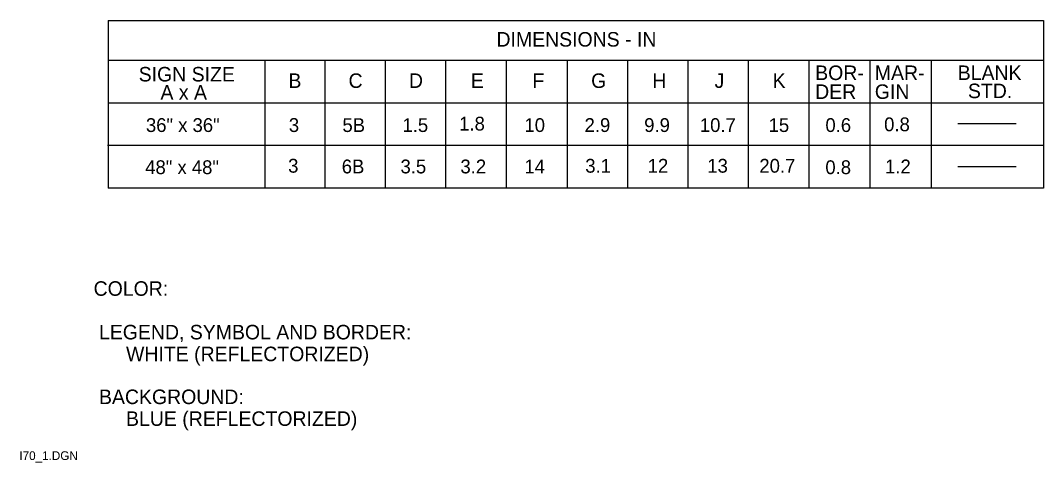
# Model space of a CAD drawing. Extents: x 0.013 to 0.194, y 0.004 to 0.259.
# Drawn here: x 0.0126 to 0.1884, y 0.0039 to 0.08 of the extents above; entities that cross this region are included whole.
import ezdxf

# ---------------------------------------------------------------- set-up
doc = ezdxf.new("R2010")
doc.units = 0
doc.layers.add('1', color=7, linetype='Continuous')
doc.layers.add('3', color=7, linetype='Continuous')

msp = doc.modelspace()

# ---------------------------------------------------------------- linework, layer by layer
at = {"layer": '3'}
for p, q in [((0.02763, 0.08), (0.18838, 0.08)), ((0.02763, 0.08), (0.02763, 0.05113)), ((0.18838, 0.08), (0.18838, 0.05113)), ((0.18838, 0.07312), (0.02763, 0.07312)), ((0.05454, 0.07306), (0.05454, 0.05106)), ((0.06488, 0.07312), (0.06488, 0.05113)), ((0.07525, 0.07312), (0.07525, 0.05113)), ((0.08563, 0.07312), (0.08563, 0.05113)), ((0.096, 0.07312), (0.096, 0.05113)), ((0.1065, 0.07312), (0.1065, 0.05113)), ((0.11688, 0.07312), (0.11688, 0.05113)), ((0.12725, 0.07312), (0.12725, 0.05113)), ((0.13762, 0.07312), (0.13762, 0.05113)), ((0.14804, 0.07306), (0.14804, 0.05106)), ((0.15854, 0.07306), (0.15854, 0.05106)), ((0.16904, 0.07306), (0.16904, 0.05106)), ((0.18838, 0.06575), (0.02763, 0.06575)), ((0.17367, 0.06225), (0.18367, 0.06225)), ((0.18838, 0.0585), (0.0275, 0.0585)), ((0.17367, 0.05488), (0.18367, 0.05488)), ((0.18838, 0.05113), (0.02763, 0.05113))]:
    msp.add_line(p, q, dxfattribs=at)

# ---------------------------------------------------------------- texts
at = {"layer": '1'}
for s, height, p in [('COLOR:', 0.0025, (0.02513, 0.03263)), (' LEGEND, SYMBOL AND BORDER:', 0.0024998, (0.02513, 0.02513)), ('      WHITE (REFLECTORIZED)', 0.0024998, (0.02513, 0.02138)), (' BACKGROUND:', 0.0024998, (0.02513, 0.014)), ('      BLUE (REFLECTORIZED)', 0.0024998, (0.02513, 0.01025))]:
    msp.add_text(s, height=height, dxfattribs=at).set_placement(p)
at = {"layer": '3'}
for s, height, p in [('DIMENSIONS - IN', 0.0024998, (0.09436, 0.0755)), ('BOR-', 0.0025, (0.14913, 0.06975)), ('MAR-', 0.0025, (0.15938, 0.06975)), ('BLANK', 0.0025, (0.17363, 0.06975)), ('SIGN SIZE', 0.0025, (0.03288, 0.0695)), ('B', 0.0025, (0.05861, 0.06839)), ('C', 0.0025, (0.06894, 0.06839)), ('D', 0.0025, (0.07932, 0.06839)), ('E', 0.0025, (0.08996, 0.06839)), ('F', 0.0025, (0.10054, 0.06839)), ('G', 0.0025, (0.11063, 0.06839)), ('H', 0.0025, (0.12114, 0.06839)), ('J', 0.0025, (0.13184, 0.06839)), ('K', 0.0025, (0.14181, 0.06839)), ('A x A', 0.0025, (0.03662, 0.06638)), ('DER', 0.0025, (0.14913, 0.0665)), ('GIN', 0.0025, (0.15938, 0.0665)), ('STD.', 0.0025, (0.17538, 0.06663)), ('1.8', 0.002375, (0.08795, 0.06106)), ('0.8', 0.002375, (0.16098, 0.06094)), ('36" x 36"', 0.002375, (0.03412, 0.06081)), ('3', 0.00238, (0.05868, 0.06081)), ('5B', 0.002375, (0.06789, 0.06081)), ('1.5', 0.002375, (0.07821, 0.06081)), ('10', 0.002375, (0.09917, 0.06081)), ('2.9', 0.002375, (0.1095, 0.06081)), ('9.9', 0.002375, (0.11975, 0.06081)), ('10.7', 0.002375, (0.12931, 0.06081)), ('15', 0.002375, (0.14113, 0.06081)), ('0.6', 0.002375, (0.15089, 0.06081)), ('48" x 48"', 0.002375, (0.034, 0.05356)), ('3', 0.00238, (0.05856, 0.05381)), ('6B', 0.002375, (0.06777, 0.05369)), ('3.5', 0.002375, (0.07787, 0.05369)), ('3.2', 0.002375, (0.08817, 0.05369)), ('14', 0.002375, (0.09917, 0.05369)), ('3.1', 0.002375, (0.10962, 0.05381)), ('12', 0.002375, (0.12035, 0.05381)), ('13', 0.002375, (0.13059, 0.05381)), ('20.7', 0.002375, (0.13954, 0.05381)), ('0.8', 0.002375, (0.15088, 0.05356)), ('1.2', 0.002375, (0.16114, 0.05369)), ('I70_1.DGN', 0.0015, (0.01238, 0.00438))]:
    msp.add_text(s, height=height, dxfattribs=at).set_placement(p)

doc.saveas('drawing.dxf')
